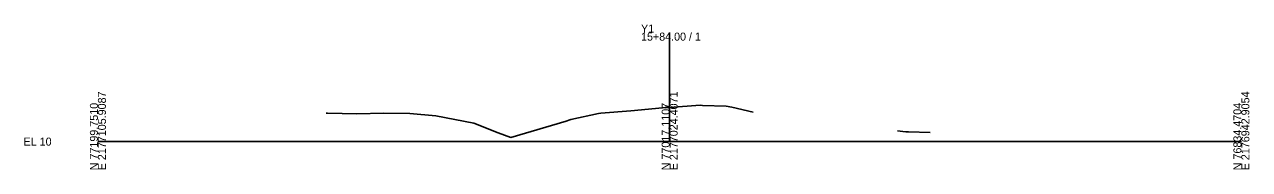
# Model space of a CAD drawing. Extents: x 2207892 to 2209721, y 61220 to 65449.
# Drawn here: x 2209292.5 to 2209721, y 61897.6 to 61948.1 of the extents above; entities that cross this region are included whole.
import ezdxf

# ---------------------------------------------------------------- set-up
doc = ezdxf.new("R2010")
doc.units = 0
for name, color, linetype in [('Exist DTM Breakline Cogo Point CELL', 7, 'Continuous'), ('Exist Roads EOP Other Cogo Elevation', 7, 'Continuous'), ('Exist Roads EOP Other Cogo Number', 7, 'Continuous')]:
    doc.layers.add(name, color=color, linetype=linetype)

msp = doc.modelspace()

# ---------------------------------------------------------------- linework, layer by layer
at = {"layer": 'Exist DTM Breakline Cogo Point CELL'}
msp.add_line((2209518.17, 61907.31), (2209518.17, 61930.1), dxfattribs=at)
at = {"layer": 'Exist Roads EOP Other Cogo Elevation'}
for points in [[(2209397.99, 61917.18), (2209398.45, 61917.24), (2209408.78, 61917.02), (2209418.23, 61917.19), (2209427.25, 61917.16), (2209436.4, 61916.3), (2209449.63, 61913.74), (2209458.17, 61910.43), (2209462.6, 61908.76), (2209481.91, 61914.46), (2209483.29, 61914.89), (2209483.65, 61914.97), (2209493.31, 61917.11), (2209494.13, 61917.18), (2209504.61, 61918.07), (2209515.69, 61919.04), (2209516.73, 61919.15), (2209517.25, 61919.18), (2209518.17, 61919.25), (2209528.83, 61919.98), (2209529.67, 61919.94), (2209537.91, 61919.72), (2209539.9, 61919.33), (2209547.38, 61917.58)], [(2209597.9, 61911.03), (2209599.72, 61910.89), (2209600.8, 61910.78), (2209601.78, 61910.75), (2209609.26, 61910.45)]]:
    msp.add_lwpolyline(points, dxfattribs=at)
at = {"layer": 'Exist Roads EOP Other Cogo Number'}
for p, q in [((2209518.17, 61907.31), (2209518.17, 61945.32)), ((2209318.17, 61907.31), (2209518.17, 61907.31)), ((2209518.17, 61907.31), (2209718.17, 61907.31))]:
    msp.add_line(p, q, dxfattribs=at)

# ---------------------------------------------------------------- texts
at = {"layer": 'Exist DTM Breakline Cogo Point CELL'}
msp.add_text('21.94', height=1, dxfattribs=at).set_placement((2209516.58, 61918.75))
at = {"layer": 'Exist Roads EOP Other Cogo Number'}
for s, p in [('Y1', (2209508.17, 61945.32)), ('15+84.00 / 1', (2209508.17, 61942.52)), ('EL 10', (2209292.17, 61905.91))]:
    msp.add_text(s, height=2.8, dxfattribs=at).set_placement(p)
for s, p in [('E 2177105.9087', (2209320.97, 61897.31)), ('E 2177024.4071', (2209520.97, 61897.31)), ('E 2176942.9054', (2209720.97, 61897.31)), ('N 77199.7510', (2209318.17, 61897.31)), ('N 77017.1107', (2209518.17, 61897.31)), ('N 76834.4704', (2209718.17, 61897.31))]:
    msp.add_text(s, height=2.8, rotation=90, dxfattribs=at).set_placement(p)

doc.saveas('drawing.dxf')
